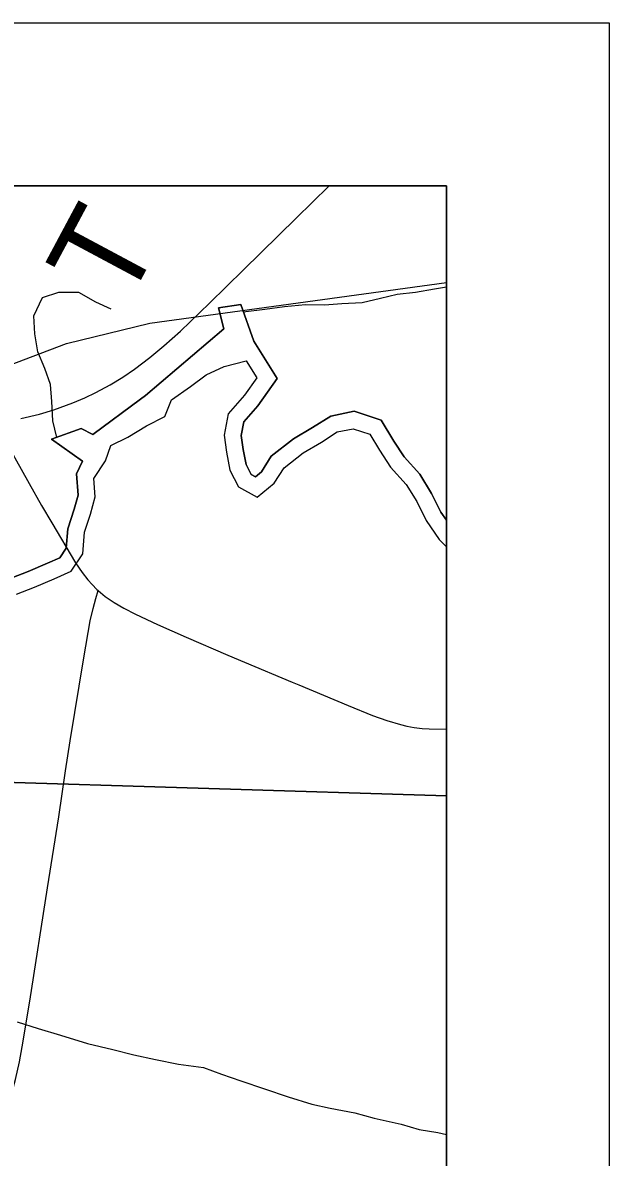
# Model space of a CAD drawing. Extents: x 0 to 34, y 0 to 22.
# Drawn here: x 8.64 to 9, y 20.304 to 21 of the extents above; entities that cross this region are included whole.
import ezdxf

# ---------------------------------------------------------------- set-up
doc = ezdxf.new("R2010")
doc.units = 0
for name, color, linetype in [('GM_X_Corporation', 7, 'Continuous'), ('GM_X_County_Road', 7, 'Continuous'), ('GM_X_Major_River', 7, 'Continuous'), ('GM_X_Minor_River', 7, 'Continuous'), ('GM_X_Rail_Line', 7, 'Continuous'), ('GM_X_State_Route', 7, 'Continuous'), ('GM_X_Township_Road_Text', 7, 'Continuous'), ('SH_Data', 7, 'Continuous')]:
    doc.layers.add(name, color=color, linetype=linetype)

msp = doc.modelspace()

# ---------------------------------------------------------------- linework, layer by layer
at = {"layer": 'GM_X_Corporation'}
for points in [[(7.97945, 19.53536), (8.40332, 19.52682), (8.9, 19.5152), (8.9, 20.9), (2.1, 20.9)], [(7.97945, 19.53536), (8.40332, 19.52682), (8.9, 19.5152), (8.9, 20.9), (3.38863, 20.9)]]:
    msp.add_lwpolyline(points, dxfattribs=at)
for points in [[(8.9, 20.52554), (8.9, 20.9), (8.47026, 20.9), (8.46216, 20.53916)], [(8.9, 19.51485), (8.9, 20.52554), (8.46216, 20.53916), (8.44047, 19.52563)]]:
    msp.add_lwpolyline(points, close=True, dxfattribs=at)
at = {"layer": 'GM_X_County_Road'}
for points in [[(8.6259, 20.75531), (8.62804, 20.74926), (8.62941, 20.74541), (8.63123, 20.74089), (8.63522, 20.73305), (8.64386, 20.71732), (8.65159, 20.70387), (8.65782, 20.69312), (8.67244, 20.66862), (8.67646, 20.66276), (8.67999, 20.65825), (8.68268, 20.65521), (8.68539, 20.65232), (8.68634, 20.65153)], [(8.61407, 20.29943), (8.61948, 20.3113), (8.62189, 20.31635), (8.62402, 20.32084), (8.62794, 20.32925), (8.63073, 20.33613), (8.63374, 20.34492), (8.63555, 20.3515), (8.63798, 20.36241), (8.63972, 20.37156), (8.64442, 20.39976), (8.65524, 20.46915), (8.66209, 20.51275), (8.66633, 20.54102), (8.66916, 20.55944), (8.67758, 20.61032), (8.68145, 20.63298), (8.68319, 20.64061), (8.68481, 20.64677), (8.68634, 20.65153)], [(8.68634, 20.65153), (8.69057, 20.64801), (8.69614, 20.64422), (8.702, 20.64083), (8.70915, 20.63717), (8.72263, 20.63083), (8.74025, 20.62309), (8.76588, 20.61194), (8.77618, 20.6076), (8.80544, 20.59546), (8.80945, 20.59378), (8.83978, 20.58098), (8.85472, 20.57491), (8.86345, 20.57179), (8.87175, 20.56945), (8.87575, 20.56842), (8.88026, 20.56757), (8.88515, 20.56703), (8.8894, 20.56671), (8.9, 20.56649)]]:
    msp.add_lwpolyline(points, dxfattribs=at)
at = {"layer": 'GM_X_Major_River'}
for points in [[(8.63324, 20.65942), (8.64325, 20.66334), (8.6551, 20.66831), (8.66278, 20.6717), (8.6667, 20.67761), (8.66761, 20.68946), (8.67161, 20.70144), (8.67399, 20.71008), (8.67301, 20.72319), (8.67672, 20.73095), (8.6577, 20.74439), (8.67579, 20.75102), (8.683, 20.74731), (8.71223, 20.76902), (8.71523, 20.77121), (8.76333, 20.81218), (8.7602, 20.82503), (8.77379, 20.82707), (8.7819, 20.8046), (8.79604, 20.78173), (8.78434, 20.76498), (8.7757, 20.75517), (8.77405, 20.74679), (8.77536, 20.73812), (8.77703, 20.72888), (8.78022, 20.72286), (8.78283, 20.72141), (8.78654, 20.7244), (8.79252, 20.73396), (8.80615, 20.74475), (8.81792, 20.75159), (8.82914, 20.75866), (8.84347, 20.76158), (8.86005, 20.75623), (8.86768, 20.74325), (8.87399, 20.73361), (8.88363, 20.723), (8.89091, 20.71123), (8.89656, 20.69978), (8.9, 20.6948)], [(8.9, 20.6948), (8.89656, 20.69978), (8.89091, 20.71123), (8.88363, 20.723), (8.87399, 20.73361), (8.86768, 20.74325), (8.86005, 20.75623), (8.84347, 20.76158), (8.82914, 20.75866), (8.81792, 20.75159), (8.80615, 20.74475), (8.79252, 20.73396), (8.78654, 20.7244), (8.78283, 20.72141), (8.78022, 20.72286), (8.77703, 20.72888), (8.77536, 20.73812), (8.77405, 20.74679), (8.7757, 20.75517), (8.78434, 20.76498), (8.79604, 20.78173), (8.7819, 20.8046), (8.77379, 20.82707), (8.7602, 20.82503), (8.76333, 20.81218), (8.71523, 20.77121), (8.71223, 20.76902), (8.683, 20.74731), (8.67579, 20.75102), (8.6577, 20.74439), (8.67672, 20.73095), (8.67301, 20.72319), (8.67399, 20.71008), (8.67161, 20.70144), (8.66761, 20.68946), (8.6667, 20.67761), (8.66278, 20.6717), (8.6551, 20.66831), (8.64325, 20.66334), (8.63324, 20.65942)], [(8.63623, 20.64945), (8.64715, 20.65373), (8.6592, 20.65878), (8.66975, 20.66344), (8.67684, 20.67412), (8.67786, 20.68739), (8.68154, 20.69842), (8.68447, 20.70906), (8.68362, 20.72042), (8.6907, 20.7311), (8.69402, 20.74061), (8.70457, 20.74564), (8.71585, 20.75258), (8.72714, 20.75838), (8.7312, 20.76865), (8.74285, 20.77673), (8.75262, 20.78403), (8.76354, 20.78907), (8.77711, 20.79263), (8.78363, 20.78208), (8.77617, 20.7714), (8.76606, 20.75992), (8.76352, 20.74702), (8.76513, 20.73642), (8.76711, 20.72546), (8.7725, 20.71528), (8.78389, 20.70896), (8.7944, 20.71741), (8.80037, 20.72694), (8.81201, 20.73616), (8.82329, 20.74271), (8.83306, 20.74888), (8.84288, 20.75088), (8.85311, 20.74757), (8.85887, 20.73778), (8.86576, 20.72724), (8.87531, 20.71674), (8.88182, 20.7062), (8.8876, 20.69451), (8.89564, 20.68285), (8.9, 20.6784)]]:
    msp.add_lwpolyline(points, dxfattribs=at)
at = {"layer": 'GM_X_Minor_River'}
for points in [[(8.77537, 20.82268), (8.78856, 20.82419), (8.80064, 20.82583), (8.81348, 20.8271), (8.8252, 20.82685), (8.83578, 20.82772), (8.84825, 20.82823), (8.85957, 20.831), (8.86975, 20.83338), (8.88108, 20.83463), (8.89278, 20.83665), (8.9, 20.83802)], [(8.6609, 20.74557), (8.65836, 20.75577), (8.65788, 20.76751), (8.65703, 20.77811), (8.65354, 20.78792), (8.64929, 20.79811), (8.64731, 20.80908), (8.64683, 20.82006), (8.65203, 20.83148), (8.66221, 20.83462), (8.6743, 20.83474), (8.68456, 20.82879), (8.69405, 20.82434), (8.69405, 20.82472)], [(8.63662, 20.3869), (8.64951, 20.38286), (8.66316, 20.37884), (8.67983, 20.37371), (8.69536, 20.37008), (8.70824, 20.36681), (8.7215, 20.36391), (8.73551, 20.36103), (8.75103, 20.35892), (8.76203, 20.35487), (8.77378, 20.35082), (8.80298, 20.3409), (8.81738, 20.3365), (8.82874, 20.33397), (8.84389, 20.3311), (8.85564, 20.32781), (8.8723, 20.3242), (8.88329, 20.3209), (8.89465, 20.31913), (8.9, 20.31776)]]:
    msp.add_lwpolyline(points, dxfattribs=at)
at = {"layer": 'GM_X_Rail_Line'}
msp.add_lwpolyline([(7.15378, 20.47014), (7.70298, 20.6401), (7.7933, 20.66371), (7.88362, 20.68116), (8.21721, 20.73452), (8.32292, 20.74991), (8.41735, 20.7612), (8.48817, 20.76325), (8.54976, 20.76632), (8.58903, 20.77378), (8.66693, 20.80326), (8.71799, 20.81574), (8.9, 20.84057)], dxfattribs=at)
at = {"layer": 'GM_X_State_Route'}
msp.add_lwpolyline([(8.63879, 20.75724), (8.65023, 20.75991), (8.65915, 20.76247), (8.67073, 20.76681), (8.67815, 20.76991), (8.68485, 20.77307), (8.69356, 20.77775), (8.70149, 20.78256), (8.70865, 20.7874), (8.718, 20.79452), (8.72658, 20.80164), (8.73672, 20.81074), (8.75462, 20.82796), (8.77556, 20.8483), (8.80788, 20.88014), (8.82779, 20.89976), (8.82803, 20.9)], dxfattribs=at)
at = {"layer": 'SH_Data'}
for p, q in [((2, 21), (9, 21)), ((9, 21), (9, 14)), ((2.1, 20.9), (8.9, 20.9)), ((8.9, 20.9), (8.9, 14.1))]:
    msp.add_line(p, q, dxfattribs=at)

# ---------------------------------------------------------------- texts
at = {"layer": 'GM_X_Township_Road_Text'}
msp.add_text('T', height=0.05682, rotation=61.867, dxfattribs=at).set_placement((8.70324, 20.82476))

doc.saveas('drawing.dxf')
